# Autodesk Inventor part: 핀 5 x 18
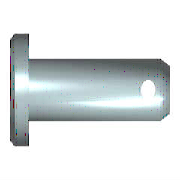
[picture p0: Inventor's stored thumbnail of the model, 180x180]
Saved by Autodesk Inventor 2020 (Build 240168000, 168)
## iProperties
Created: 2012-02
Part Number: 핀 5 x 18
Material: 강철
Description: 머리가 있는 클레비스 핀
Document SubType Name: Modeling
Standard: ISO 2341
Designer: test
Standard Revision: Second edition 1986-11-01
Standards Organization: ISO
Language: ko-KR
Size Designation: B - 5 x 18
Categories: <MemberInstance><Categories><Category DisplayName="조임쇠" InternalName="e4da775c-781d-43d5-af7c-5136215cf5a6" Mnemonic="FSTN"><Category DisplayName="핀" InternalNa
Density: 7.85 g/cm^3
Appearance: 강철
IsCustomPart: 1
Author: test
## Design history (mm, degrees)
sketch "스케치1"
  geometry: L1 (-1.6, 0)-(-1.6, 4); L2 (-1.6, 4)-(0, 4); L3 (0, 4)-(0, 2.5); L4 (0, 2.5)-(18, 2.5); L5 (18, 2.5)-(18, 0); L6 (-1.6, 0)-(18, 0); L7 (-4, 0)-(17, 0) reference; L8 (0, -0.98)-(0, 3.08) reference; C1 r 0.6 at (15.1, 0)
  constraints: 12 end point, 3 parallel, 2 collinear, 2 perpendicular, 1 centre point, 1 point on line, 1 vertical
  dimensions: "d0" = 5 diameter of L4 L6 (= NND); "d1" = 8 diameter of L2 L6 (= KOD); "d2" = 1.6 distance of L1.end L2.end (= KOH); "d3" = 18 distance of L3.end L4.end (= NLG); "d5" = 2.9 distance from line of L5 C1.centre (= DIST); "d6" = 1.2 diameter of C1 (= BOR)
revolve "본체" stored, may be unused: angle "d4" = 90 deg
extrude "구멍" cut sketch "스케치1" extent not by distance; stored distance "d7" = 5 (= NND); taper "d8" = 0 deg
workaxis "Work Axis1"
workplane "Work Plane1"
body "Solid1"
chamfer "모따기1" distance "d9" = 1 (= PHH2); stored, may be unused: angle "d10" = 45 deg (= FAWI2), second distance "d16" = 1 (= PHH2)
chamfer "모따기2" distance "d11" = 2 (= PHH1); stored, may be unused: angle "d12" = 30 deg (= FAWI1), second distance "d17" = 2 (= PHH1)
other parameters: "PHH1" = 2 [user parameter; used in 2 equation terms], "PHH2" = 1 [user parameter; used in 2 equation terms], "KOD" = 8 [user parameter; used in 1 equation term], "KOH" = 1.6 [user parameter; used in 1 equation term], "NND" = 5 [user parameter; used in 2 equation terms], "FAWI1" = 30 deg [user parameter; used in 1 equation term], "FAWI2" = 45 deg [user parameter; used in 1 equation term], "DIST" = 2.9 [user parameter; used in 1 equation term], "BOR" = 1.2 [user parameter; used in 1 equation term], "NLG" = 18 [user parameter; used in 1 equation term], "d13" = 0, "d14" = 0, "d27" = 0, "d28" = 0, "d29" = 0, "d30" = 0, "d31" = 0
